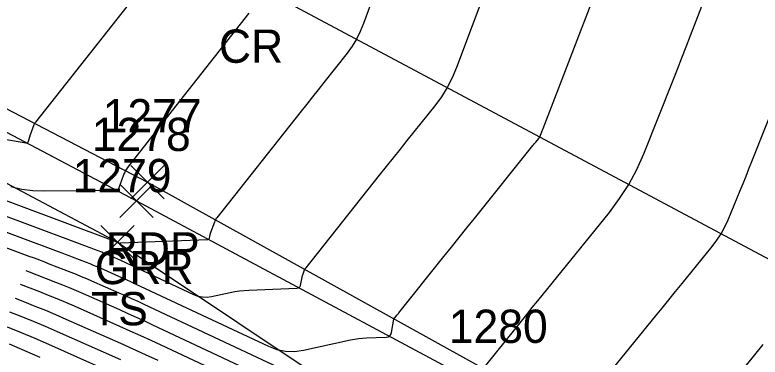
# Model space of a CAD drawing. Extents: x 1650836 to 1652450, y 332578 to 333908.
# Drawn here: x 1652137.1 to 1652181.92, y 332746.42 to 332766.98 of the extents above; entities that cross this region are included whole.
import ezdxf

# ---------------------------------------------------------------- set-up
doc = ezdxf.new("R2010")
doc.units = 0
for name, color, linetype in [('L_A', 7, 'Continuous'), ('L_I', 7, 'Continuous'), ('L_TIC', 7, 'Continuous'), ('LELB', 7, 'Continuous'), ('LSOGCMA', 7, 'Continuous'), ('LSOGCMI', 7, 'Continuous'), ('P_A', 7, 'Continuous'), ('P_I', 7, 'Continuous'), ('P_TIC', 7, 'Continuous'), ('PET', 7, 'Continuous'), ('PRC', 7, 'Continuous'), ('R_A', 7, 'Continuous'), ('R_I', 7, 'Continuous'), ('R_TIC', 7, 'Continuous'), ('RGR', 7, 'Continuous')]:
    doc.layers.add(name, color=color, linetype=linetype)

msp = doc.modelspace()

# ---------------------------------------------------------------- linework, layer by layer
at = {"layer": 'L_TIC'}
for points in [[(1652142.274, 332752.324), (1652144.274, 332754.324)], [(1652144.274, 332752.324), (1652142.274, 332754.324)]]:
    msp.add_lwpolyline(points, dxfattribs=at)
at = {"layer": 'LELB'}
msp.add_lwpolyline([(1651844.759, 332915.941), (1651880.379, 332894.976), (1651917.082, 332874.787), (1651949.824, 332853.945), (1651967.074, 332844.342), (1652000.53, 332828.254), (1652035.357, 332809.776), (1652067.23, 332793.489), (1652106.029, 332773.108), (1652143.274, 332753.324), (1652172.167, 332734.049)], dxfattribs=at)
at = {"layer": 'LSOGCMA'}
msp.add_lwpolyline([(1652143.474, 332746.245), (1652139.656, 332747.932), (1652138.936, 332748.245), (1652138.212, 332748.55), (1652137.485, 332748.847), (1652136.804, 332749.115)], dxfattribs=at)
at = {"layer": 'LSOGCMI'}
for points in [[(1652110.901, 332763.523), (1652139.705, 332752.766), (1652139.917, 332752.687), (1652140.128, 332752.606), (1652140.34, 332752.526), (1652140.551, 332752.444), (1652141.395, 332752.117), (1652141.606, 332752.034), (1652141.815, 332751.948), (1652142.024, 332751.86), (1652142.231, 332751.77), (1652143.332, 332751.284), (1652143.584, 332751.172), (1652143.835, 332751.058), (1652144.086, 332750.943), (1652144.336, 332750.826), (1652152.35, 332747.068), (1652152.863, 332746.874), (1652153.387, 332746.77), (1652153.921, 332746.755), (1652154.465, 332746.83), (1652157.283, 332747.444), (1652157.521, 332747.491), (1652157.76, 332747.527), (1652158.001, 332747.553), (1652158.243, 332747.568), (1652159.43, 332747.617), (1652159.551, 332747.638), (1652159.645, 332747.692), (1652159.711, 332747.777), (1652159.75, 332747.894), (1652159.901, 332748.685), (1652159.903, 332748.693), (1652159.907, 332748.705), (1652159.909, 332748.71), (1652159.912, 332748.714), (1652160.084, 332748.931), (1652160.114, 332748.968), (1652160.143, 332749.005), (1652160.172, 332749.042), (1652160.202, 332749.078), (1652162.91, 332752.454), (1652163.371, 332753.029), (1652163.832, 332753.604), (1652164.293, 332754.178), (1652164.754, 332754.753), (1652168.259, 332759.124), (1652168.301, 332759.176), (1652168.342, 332759.228), (1652168.384, 332759.28), (1652168.426, 332759.332), (1652168.609, 332759.557), (1652168.642, 332759.602), (1652168.672, 332759.648), (1652168.698, 332759.696), (1652168.72, 332759.747), (1652168.802, 332759.953), (1652168.823, 332760.004), (1652168.843, 332760.056), (1652168.863, 332760.108), (1652168.883, 332760.159), (1652173.712, 332772.711)], [(1652166.551, 332771.514), (1652163.667, 332763.821), (1652163.409, 332763.207), (1652163.105, 332762.62), (1652162.756, 332762.059), (1652162.36, 332761.524), (1652160.685, 332759.436), (1652160.266, 332758.914), (1652159.848, 332758.391), (1652159.431, 332757.867), (1652159.015, 332757.344), (1652154.604, 332751.784), (1652154.568, 332751.735), (1652154.537, 332751.684), (1652154.51, 332751.631), (1652154.488, 332751.575), (1652154.406, 332751.347), (1652154.386, 332751.29), (1652154.369, 332751.232), (1652154.355, 332751.174), (1652154.342, 332751.114), (1652154.267, 332750.722), (1652154.242, 332750.647), (1652154.2, 332750.592), (1652154.139, 332750.558), (1652154.061, 332750.544), (1652151.171, 332750.424), (1652150.888, 332750.407), (1652150.606, 332750.377), (1652150.326, 332750.334), (1652150.048, 332750.28), (1652148.937, 332750.038), (1652148.662, 332750), (1652148.392, 332750.007), (1652148.127, 332750.06), (1652147.867, 332750.158), (1652143.812, 332752.06), (1652143.685, 332752.119), (1652143.558, 332752.177), (1652143.431, 332752.235), (1652143.303, 332752.292), (1652142.746, 332752.538), (1652142.641, 332752.583), (1652142.536, 332752.628), (1652142.43, 332752.671), (1652142.323, 332752.713), (1652141.896, 332752.879), (1652141.789, 332752.92), (1652141.682, 332752.961), (1652141.575, 332753.001), (1652141.468, 332753.042), (1652110.315, 332764.675)], [(1652165.428, 332745.904), (1652167.244, 332748.169), (1652167.57, 332748.575), (1652167.896, 332748.981), (1652168.223, 332749.386), (1652168.551, 332749.791), (1652172.861, 332755.115), (1652173.477, 332755.937), (1652174.027, 332756.798), (1652174.51, 332757.699), (1652174.926, 332758.638), (1652176.687, 332763.052), (1652176.953, 332763.723), (1652177.217, 332764.395), (1652177.479, 332765.067), (1652177.74, 332765.74), (1652179.24, 332769.64)], [(1652145.047, 332769.019), (1652138.333, 332760.539), (1652138.306, 332760.502), (1652138.282, 332760.463), (1652138.261, 332760.422), (1652138.244, 332760.379), (1652138.003, 332759.707), (1652137.997, 332759.689), (1652137.991, 332759.67), (1652137.985, 332759.651), (1652137.979, 332759.633), (1652137.901, 332759.364), (1652137.882, 332759.32), (1652137.853, 332759.292), (1652137.815, 332759.278), (1652137.767, 332759.28), (1652136.502, 332759.498)], [(1652158.767, 332768.388), (1652158.066, 332766.457), (1652157.873, 332765.984), (1652157.645, 332765.531), (1652157.38, 332765.098), (1652157.08, 332764.684), (1652155.686, 332762.914), (1652155.347, 332762.484), (1652155.008, 332762.055), (1652154.669, 332761.626), (1652154.329, 332761.197), (1652149.24, 332754.783), (1652149.197, 332754.724), (1652149.159, 332754.662), (1652149.126, 332754.597), (1652149.098, 332754.529), (1652148.854, 332753.849), (1652148.841, 332753.813), (1652148.831, 332753.776), (1652148.821, 332753.739), (1652148.813, 332753.701), (1652148.785, 332753.55), (1652148.773, 332753.516), (1652148.755, 332753.492), (1652148.728, 332753.477), (1652148.693, 332753.471), (1652143.463, 332753.255), (1652143.456, 332753.254), (1652143.449, 332753.254), (1652143.442, 332753.253), (1652143.436, 332753.251), (1652143.409, 332753.245), (1652143.403, 332753.245), (1652143.396, 332753.245), (1652143.39, 332753.246), (1652143.384, 332753.248), (1652143.287, 332753.294), (1652143.275, 332753.299), (1652143.257, 332753.307), (1652143.231, 332753.317), (1652117.381, 332762.971)], [(1652136.859, 332756.663), (1652137.52, 332756.515), (1652138.191, 332756.429), (1652138.874, 332756.404), (1652142.922, 332756.44), (1652142.962, 332756.439), (1652143.001, 332756.437), (1652143.04, 332756.433), (1652143.078, 332756.427), (1652143.293, 332756.39), (1652143.301, 332756.39), (1652143.307, 332756.392), (1652143.312, 332756.397), (1652143.316, 332756.405), (1652143.329, 332756.45), (1652143.332, 332756.46), (1652143.362, 332756.545), (1652143.663, 332757.384), (1652143.709, 332757.497), (1652143.763, 332757.606), (1652143.826, 332757.71), (1652143.898, 332757.809), (1652147.021, 332761.791), (1652147.542, 332762.454), (1652148.063, 332763.117), (1652148.584, 332763.779), (1652149.105, 332764.442), (1652151.191, 332767.091)], [(1652171.029, 332743.197), (1652175.624, 332748.868), (1652176.024, 332749.362), (1652176.425, 332749.856), (1652176.826, 332750.349), (1652177.228, 332750.841), (1652179.044, 332753.064), (1652179.328, 332753.439), (1652179.582, 332753.832), (1652179.807, 332754.242), (1652180.001, 332754.67), (1652180.72, 332756.418), (1652180.899, 332756.856), (1652181.077, 332757.293), (1652181.253, 332757.732), (1652181.428, 332758.171), (1652184.827, 332766.726)], [(1652111.487, 332762.37), (1652137.942, 332752.491), (1652138.258, 332752.372), (1652138.574, 332752.252), (1652138.89, 332752.131), (1652139.206, 332752.009), (1652140.467, 332751.52), (1652140.782, 332751.396), (1652141.095, 332751.269), (1652141.406, 332751.137), (1652141.716, 332751.002), (1652143.36, 332750.276), (1652143.737, 332750.109), (1652144.112, 332749.939), (1652144.487, 332749.767), (1652144.861, 332749.593), (1652156.833, 332743.978)], [(1652137.751, 332751.617), (1652137.861, 332751.575), (1652139.539, 332750.924), (1652139.957, 332750.759), (1652140.374, 332750.589), (1652140.789, 332750.414), (1652141.201, 332750.235), (1652143.389, 332749.268), (1652143.89, 332749.045), (1652144.39, 332748.819), (1652144.888, 332748.591), (1652145.385, 332748.359), (1652162.261, 332740.444)], [(1652167.854, 332736.833), (1652145.91, 332747.126), (1652145.289, 332747.415), (1652144.667, 332747.7), (1652144.043, 332747.982), (1652143.417, 332748.261), (1652140.686, 332749.467), (1652140.171, 332749.691), (1652139.653, 332749.909), (1652139.133, 332750.122), (1652138.611, 332750.328), (1652137.436, 332750.783)], [(1652137.12, 332749.95), (1652137.683, 332749.731), (1652138.309, 332749.484), (1652138.933, 332749.23), (1652139.553, 332748.968), (1652140.171, 332748.7), (1652143.445, 332747.253), (1652144.196, 332746.919), (1652144.944, 332746.581), (1652145.69, 332746.239)], [(1652143.502, 332745.238), (1652139.141, 332747.165), (1652138.318, 332747.523), (1652137.491, 332747.871), (1652136.661, 332748.21)], [(1652138.626, 332746.397), (1652137.701, 332746.8), (1652136.771, 332747.191)], [(1652182.096, 332747.166), (1652181.592, 332746.549), (1652181.088, 332745.931)]]:
    msp.add_lwpolyline(points, dxfattribs=at)
at = {"layer": 'P_TIC'}
for points in [[(1652144.079, 332755.921), (1652146.079, 332757.921)], [(1652146.079, 332755.921), (1652144.079, 332757.921)]]:
    msp.add_lwpolyline(points, dxfattribs=at)
at = {"layer": 'PET'}
msp.add_lwpolyline([(1651764.546, 332972.615), (1651784.506, 332958.597), (1651809.702, 332941.927), (1651846.26, 332918.158), (1651881.765, 332897.162), (1651918.116, 332876.642), (1651951.432, 332858.415), (1651975.296, 332845.48), (1652002.223, 332831.337), (1652037.173, 332813.417), (1652069.296, 332796.636), (1652107.428, 332776.545), (1652145.079, 332756.921), (1652175.234, 332740.226), (1652190.754, 332731.861), (1652206.573, 332723.523), (1652239.422, 332706.921), (1652282.404, 332684.366), (1652332.494, 332658.525), (1652365.542, 332641.171), (1652388.914, 332629.021)], dxfattribs=at)
at = {"layer": 'PRC'}
msp.add_lwpolyline([(1651773.612, 332982.822), (1651792.672, 332969.525), (1651816.542, 332953.47), (1651853.779, 332929.89), (1651888.829, 332909.027), (1651925.09, 332888.189), (1651957.726, 332870.48), (1651982.519, 332857.297), (1652019.654, 332837.681), (1652042.767, 332825.192), (1652076.048, 332808.311), (1652114.48, 332787.851), (1652150.944, 332769.103), (1652185.791, 332750.516), (1652225.777, 332729.89), (1652246.28, 332718.635), (1652288.707, 332696.529), (1652339.002, 332669.86), (1652372.556, 332652.699), (1652395.364, 332640.33)], dxfattribs=at)
at = {"layer": 'R_TIC'}
for points in [[(1652143.421, 332754.8), (1652145.421, 332756.8)], [(1652145.421, 332754.8), (1652143.421, 332756.8)]]:
    msp.add_lwpolyline(points, dxfattribs=at)
at = {"layer": 'RGR'}
msp.add_lwpolyline([(1651963.926, 332842.71), (1651967.074, 332844.342), (1651975.028, 332844.451), (1652001.752, 332830.477), (1652036.76, 332812.304), (1652068.698, 332795.548), (1652107.135, 332775.504), (1652144.421, 332755.8), (1652165.98, 332744.268), (1652170.761, 332738.792), (1652172.167, 332734.049)], dxfattribs=at)

# ---------------------------------------------------------------- texts
at = {"layer": 'L_A'}
msp.add_text('TS', height=2, dxfattribs=at).set_placement((1652141.684, 332748.324))
at = {"layer": 'L_I'}
msp.add_text('1279', height=2, dxfattribs=at).set_placement((1652140.574, 332756.324))
at = {"layer": 'P_A'}
for s, p in [('CR', (1652149.377, 332764.103)), ('RDP', (1652142.567, 332751.921))]:
    msp.add_text(s, height=2, dxfattribs=at).set_placement(p)
at = {"layer": 'P_I'}
msp.add_text('1277', height=2, dxfattribs=at).set_placement((1652142.386, 332759.921))
at = {"layer": 'R_A'}
msp.add_text('GRR', height=2, dxfattribs=at).set_placement((1652141.91, 332750.8))
at = {"layer": 'R_I'}
for s, p in [('1278', (1652141.729, 332758.8)), ('1280', (1652163.201, 332747.268))]:
    msp.add_text(s, height=2, dxfattribs=at).set_placement(p)

doc.saveas('drawing.dxf')
